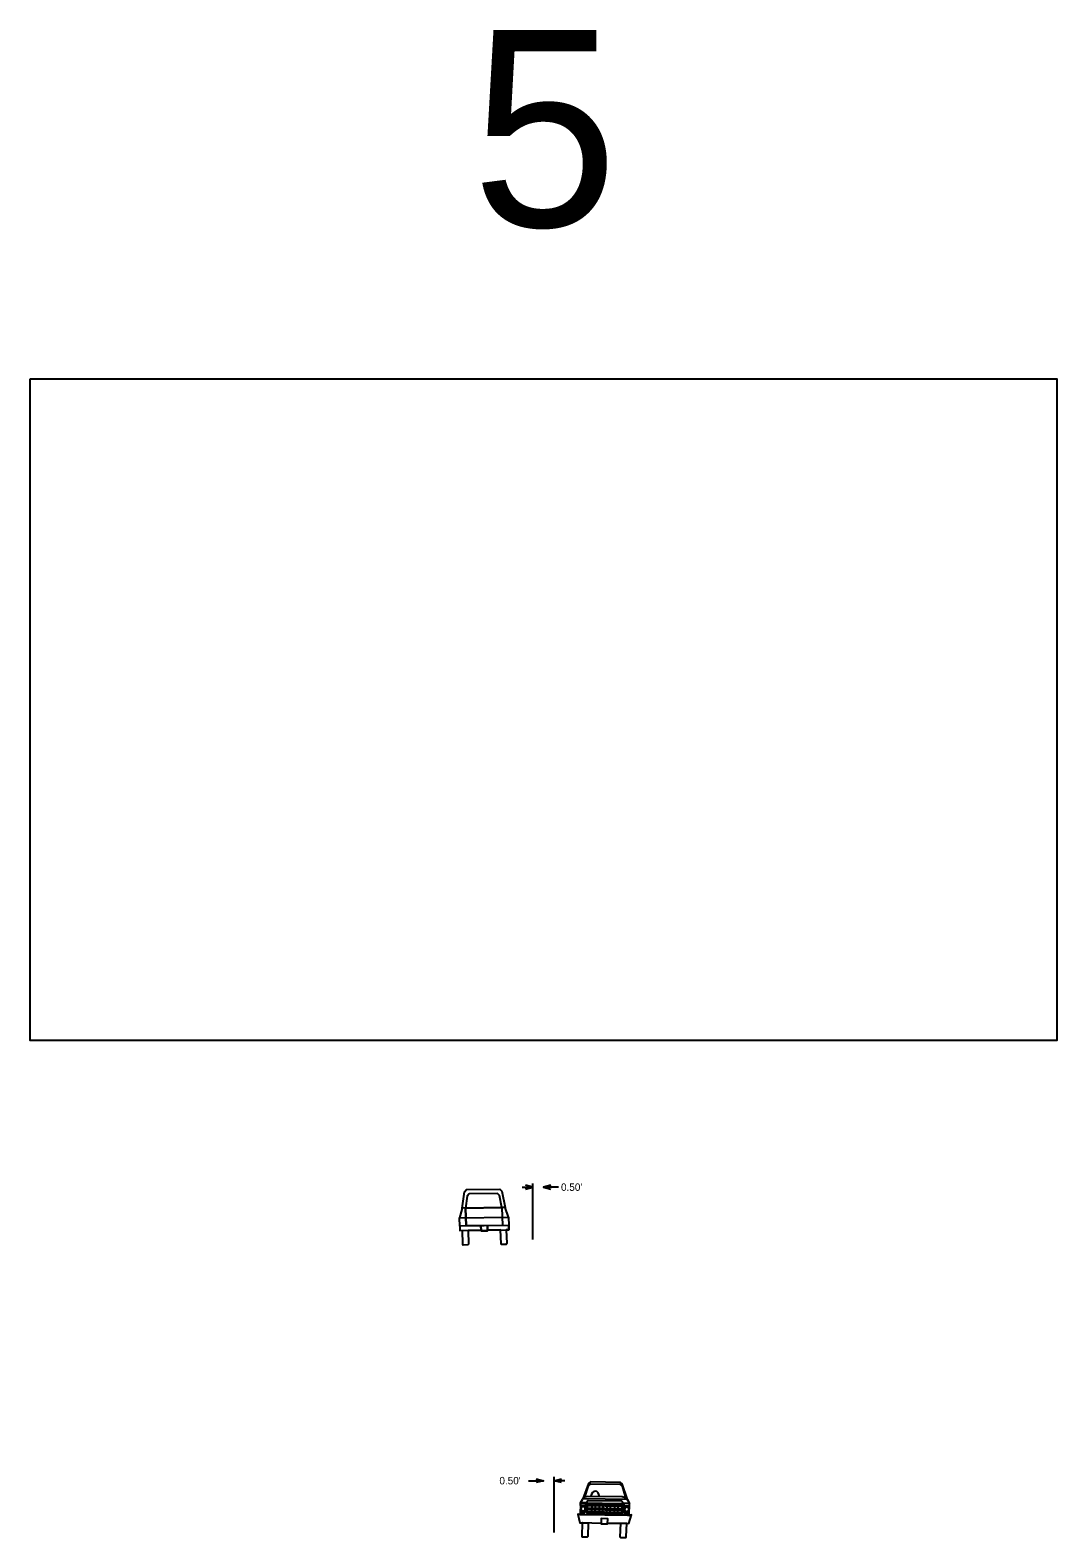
# Model space of a CAD drawing. Extents: x 10133 to 81668, y 4692 to 11018.
# Drawn here: x 24533 to 27668, y 6405 to 11009 of the extents above; entities that cross this region are included whole.
import ezdxf

# ---------------------------------------------------------------- set-up
doc = ezdxf.new("R2010")
doc.units = 0
for name, color, linetype in [('Level 7', 7, 'Continuous'), ('Level 8', 7, 'Continuous'), ('SheetBorder', 7, 'Continuous'), ('SheetText', 7, 'Continuous')]:
    doc.layers.add(name, color=color, linetype=linetype)

msp = doc.modelspace()

# ---------------------------------------------------------------- linework, layer by layer
at = {"layer": 'Level 7'}
for p, q in [((26035.3, 7476), (26067.6, 7476)), ((26067.6, 7316.2), (26067.6, 7487.4)), ((26145.4, 7476), (26100, 7476)), ((26132.4, 6422), (26132.4, 6591.1)), ((26054.6, 6579.7), (26100, 6579.7)), ((26164.8, 6579.7), (26132.4, 6579.7))]:
    msp.add_line(p, q, dxfattribs=at)
for points in [[(26044.9, 7470.4), (26067.6, 7476), (26044.9, 7481.7)], [(26122.7, 7481.7), (26100, 7476), (26122.7, 7470.4)], [(26077.3, 6585.4), (26100, 6579.7), (26077.3, 6574)], [(26155.2, 6574), (26132.4, 6579.7), (26155.2, 6585.4)]]:
    msp.add_lwpolyline(points, dxfattribs=at)
at = {"layer": 'Level 8'}
for p, q in [((25844.3, 7343.5), (25844.3, 7343.5)), ((26211, 6451.5), (26211, 6451.5)), ((26361.5, 6473.3), (26211.7, 6475.4)), ((26339.8, 6477.8), (26361.5, 6473.3))]:
    msp.add_line(p, q, dxfattribs=at)
for points in [[(25851.8, 7411.9), (25859.2, 7462.3), (25865, 7468.7), (25966.9, 7470.3), (25973, 7464), (25982.9, 7413.8), (25851.8, 7411.9), (25845.5, 7389.7), (25843.4, 7382.2), (25993.2, 7384.5), (25983.1, 7413.9), (25972.9, 7413.7), (25965.4, 7450.4), (25959.3, 7456.7), (25873.2, 7455.4), (25867.4, 7448.9), (25862, 7412), (25972.9, 7413.7), (25974.4, 7359.3), (25863.5, 7357.7), (25862, 7412), (25863.5, 7357.7), (25844.1, 7357.2), (25843.4, 7382.2), (25993.2, 7384.5), (25993.9, 7359.4), (25844.1, 7357.2), (25844.3, 7343.5), (25909.4, 7344.5), (25909, 7357.8), (25909.5, 7342.3), (25929.3, 7342.6), (25928.9, 7358.1), (25929.3, 7344.8), (25994.3, 7345.8), (25993.9, 7359.4), (25994.3, 7345.8), (25986.4, 7345.9), (25987.6, 7304), (25986.4, 7301.4), (25972.2, 7301.2), (25970.3, 7303.5), (25969.1, 7345.4), (25929.3, 7344.8), (25929.3, 7342.6), (25909.5, 7342.3), (25909.4, 7344.5), (25869.6, 7343.9), (25870.7, 7302), (25868.9, 7299.6), (25854.7, 7299.4), (25853.4, 7301.9), (25852.3, 7343.8)], [(26233.8, 6479.6), (26247.8, 6479.4), (26248.5, 6507.9), (26257.4, 6507.8), (26256.9, 6479.4), (26270.9, 6479.1), (26271.4, 6507.5), (26280.7, 6507.4), (26279.8, 6479), (26293.9, 6478.7), (26294.3, 6507.1), (26303.6, 6507), (26302.8, 6478.6), (26316.7, 6478.3), (26317.6, 6506.7), (26326.6, 6506.7), (26325.9, 6478.1), (26339.8, 6477.8), (26340.2, 6489.2), (26234.1, 6491), (26234.2, 6496.7), (26340.2, 6494.9), (26340.4, 6500.7), (26234.4, 6502.5), (26234.6, 6508.2), (26340.5, 6506.4), (26339.8, 6477.8), (26233.8, 6479.6), (26234.6, 6511.9), (26212.8, 6512.1), (26345.7, 6510.2), (26346.7, 6502.4), (26362.4, 6502.2), (26346.7, 6502.4), (26346.1, 6483), (26361.8, 6482.7), (26211.9, 6484.9), (26227.6, 6484.6), (26228.2, 6504), (26229.7, 6511.9), (26228.2, 6504), (26212.5, 6504.3), (26212.8, 6512.1), (26211.7, 6475.4), (26204.6, 6477.9), (26211, 6451.5), (26236.2, 6451.1), (26235.1, 6409.1), (26233.2, 6407.1), (26218.9, 6407.1), (26217.7, 6409.7), (26218.9, 6451.6), (26276.1, 6450.5), (26276.1, 6448.3), (26295.8, 6448.1), (26296.2, 6463.7), (26276.5, 6463.8), (26276.1, 6448.3), (26295.8, 6448.1), (26295.8, 6450.3), (26353.1, 6449.7), (26351.9, 6407.8), (26350.6, 6405.2), (26336.4, 6405.5), (26334.6, 6407.7), (26335.7, 6449.7), (26361, 6449.3), (26368.9, 6475.5), (26361.5, 6473.3), (26362.6, 6510), (26356.2, 6522.3), (26362.6, 6510), (26345.7, 6510.2), (26343.7, 6511.5), (26341.5, 6515.4), (26339.5, 6517), (26236, 6518.4), (26234.1, 6517.2), (26231.7, 6513.2), (26229.7, 6511.9), (26212.8, 6512.1), (26218.7, 6522.7), (26219.9, 6524.4), (26222.8, 6525.4), (26353.3, 6523.5), (26350.3, 6527.2), (26340.7, 6530.1), (26235.8, 6531.8), (26225.9, 6529.2), (26237.9, 6564.1), (26244.9, 6570.3), (26333.6, 6569), (26340.4, 6562.7), (26350.3, 6527.2), (26353.3, 6523.5), (26356.2, 6522.3), (26340.6, 6570.2), (26335.4, 6574.7), (26243.6, 6576.3), (26237.9, 6571.6), (26219.9, 6524.4)]]:
    msp.add_lwpolyline(points, dxfattribs=at)
msp.add_ellipse((26257.6, 6530), major_axis=(0.7, 17.7), ratio=0.738443, start_param=4.836659, end_param=7.727368, dxfattribs=at)
for centre, major_axis, ratio in [((26220.8, 6493.9), (-0.31, -7.52), 0.738443), ((26354.1, 6492.3), (-0.31, -7.52), 0.738443), ((26220.2, 6481.2), (-5.77, -0.77), 0.492933), ((26353.7, 6478.4), (5.73, -0.9), 0.496306)]:
    msp.add_ellipse(centre, major_axis=major_axis, ratio=ratio, dxfattribs=at)
at = {"layer": 'SheetBorder'}
msp.add_lwpolyline([(24532.5, 9944), (27667.5, 9944), (27667.5, 7924), (24532.5, 7924)], close=True, dxfattribs=at)

# ---------------------------------------------------------------- texts
at = {"layer": 'Level 7'}
for p in [(26153.5, 7464.8), (25965.4, 6568.5)]:
    msp.add_text("0.50'", height=22.71, dxfattribs=at).set_placement(p)
at = {"layer": 'SheetText'}
msp.add_text('5', height=600, dxfattribs=at).set_placement((25880.7, 10409.2))

doc.saveas('drawing.dxf')
